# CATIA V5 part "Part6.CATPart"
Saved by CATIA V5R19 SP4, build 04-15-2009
Part number: axe coté carosserie
Bounding box of the stored display mesh (mm): x 0 to 200, y -12.997 to 13.003, z -12.655 to 12.95
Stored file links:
  C:\Users\Romain\Desktop\projet CFAO\Part6.CATPart
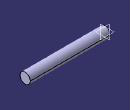
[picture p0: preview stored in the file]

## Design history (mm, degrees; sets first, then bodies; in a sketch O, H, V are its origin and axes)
Body1 (main body)
  Sketch1 on yz-plane, origin (0, 0, 0), H (0, 1, 0), V (0, 0, 1)
    circle A1 centre (0.0034, 0.1475) radius 13
    radius A1 = 13
  Pad1: profile Sketch1, direction (1, 0, 0), length 200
